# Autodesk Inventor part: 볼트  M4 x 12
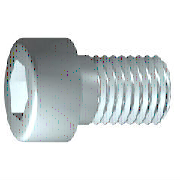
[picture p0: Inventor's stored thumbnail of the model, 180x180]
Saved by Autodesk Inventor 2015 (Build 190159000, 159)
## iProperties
IsCustomPart: 0
Created: 2015-12
Part Number: 볼트  M4 x 12
Material: 일반
Description: 6각머리 태핑 나사
Document SubType Name: Modeling
Standard: KS B 1003
Designer: mdu
Standards Organization: KS
Language: ko-KR
Size Designation: M 4 x 12
Categories: <MemberInstance><Categories><Category DisplayName="조임쇠" InternalName="e4da775c-781d-43d5-af7c-5136215cf5a6" Mnemonic="FSTN"><Category DisplayName="볼트" InternalN
Density: 1 g/cm^3
Mass: 0.284306 g
Surface Area: 3.30853 cm^2
Volume: 0.284306 cm^3
Appearance: 기본값
Author: mdu
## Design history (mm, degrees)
sketch "스케치1"
  geometry: L1 (-1, 0)-(12, 0); L2 (12, 0)-(12, 2); L3 (12, 2)-(1.75, 2); L4 (1.75, 2)-(1.32, 2); L5 (1.32, 2)-(0, 2); L6 (0, 2)-(0, 3.5); L7 (0, 3.5)-(-4, 3.5); L8 (-4, 3.5)-(-4, 1.732); L9 (-4, 1.732)-(-2, 1.732); L10 (-2, 1.732)-(-1, 0); L11 (-7.2, 0)-(15.2, 0) reference; L12 (0, -0.7)-(0, 4.2) reference; L13 (1.75, 2)-(0, 2)
  constraints: 22 end point, 6 parallel, 2 collinear, 2 perpendicular, 1 horizontal, 1 point on line
  dimensions: "d1" = 10.25 distance from line of L3.end L2 (= GEL); "d2" = 0.42952 distance of L4.end L3.end (computed from GAL); "d3" = 4 distance between parallel lines of L8 L6 (= KOH); "d4" = 2 distance of L8.end L9.end (= INTI); "d5" = 60 deg angle of L10 L1; "d6" = 4 diameter of L3 L1 (= GD); "d7" = 4 diameter of L5 L1 (= BDM); "d8" = 3.4641 diameter of L9 L1 (= 1.1547 x SW); "d9" = 7 diameter of L7 L1 (= KOD); "d26" = 12 distance between parallel lines of L12 L2 (= NLG)
revolve "본체" sketch "스케치1" stored, may be unused: angle "d10" = 90 deg
sketch "스케치2"
  geometry: L1 (0, -4.9)-(0, 4.9) reference; L2 (-4.9, 0)-(4.9, 0) reference; L3 (1.732, 0)-(0.866, -1.5); L4 (0.866, -1.5)-(-0.866, -1.5); L5 (-0.866, -1.5)-(-1.732, 0); L6 (-1.732, 0)-(-0.866, 1.5); L7 (-0.866, 1.5)-(0.866, 1.5); L8 (0.866, 1.5)-(1.732, 0); 2 further points
  constraints: 12 end point, 1 coincident, 1 horizontal alignment, 1 point on line, 12 other
extrude "슬롯" join sketch "스케치2" stored distance "d11" = 10; taper "d12" = 0 deg
workplane "Work Plane1"
fillet "Fillet2" dims "d30" = 0.1 (= R)
body "Solid1"
fillet "모깎기1" dims "d17" = 0.4 (= RR)
feature "스레드" dims "d13" = 10.25 (= GEL), "d14" = 0
chamfer "모따기1" distance "d15" = 0.42941 (= -0.5 x SPD + 0.5 x GD); stored, may be unused: second distance "d16" = 0.42941 (= GUL), angle "d27" = 45 deg
other parameters: "GD" = 4 (= NND) [user parameter; used in 2 equation terms], "NLG" = 12 [user parameter; used in 1 equation term], "GEL" = 10.25 [user parameter; used in 2 equation terms], "KOD" = 7 [user parameter; used in 1 equation term], "KOH" = 4 [user parameter; used in 1 equation term], "INTI" = 2 [user parameter; used in 1 equation term], "GAL" = 0.42941 (= 0.61345 x PTC) [user parameter; used in 1 equation term], "GUL" = 0.42941 (= 0.61345 x PTC) [user parameter; used in 1 equation term], "BDM" = 4 (= NND) [user parameter; used in 1 equation term], "SW" = 3 [user parameter; used in 2 equation terms], "RR" = 0.4 [user parameter; used in 1 equation term], "SPD" = 3.14117 (= NND - 1.2269 x PTC) [user parameter; used in 1 equation term], "d19" = 0, "d28" = 0, "d29" = 0, "R" = 0.1 [user parameter; used in 1 equation term], "PHH" = 0.2 [user parameter], "GD1" = 3.14117 (= THREADDIA - 1.2269 x PTC) [user parameter], "THREADDIA" = 4 [user parameter; used in 1 equation term], "FAWI" = 45 deg [user parameter], "TPU" = 14.28571 (computed from PTC) [user parameter], "PTC" = 0.7 [user parameter; used in 5 equation terms], "NND" = 4 [user parameter; used in 3 equation terms], "TOA" = 30 deg [user parameter], "E0" = 3.465 (= 1.155 x SW) [user parameter]
